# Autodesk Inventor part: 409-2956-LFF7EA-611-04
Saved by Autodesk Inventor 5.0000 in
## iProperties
Created: 2010-06
Part Number: 409-2956-LFF7EA-611-04
Cost Center: 0 lbmass
Material: A36 STEEL PLATE
Document SubType Name: Sheet Metal
Designer: S. Boerckel
Authority: 0 in^3
Mass: 31443.9 g
Surface Area: 6667.73 cm^2
Volume: 4000.49 cm^3
Density: 7.86 g/cm^3
Flat Pattern Width: 26.67 cm
Flat Pattern Length: 118.11 cm
Flat Pattern Area: 3149.99 cm^2
Sheet Metal Rule: 1/2"Thk
Sheet Metal Width: 16.0000 in
Sheet Metal Length: 80.0000 in^2
Description: PUMP FOOT PLATE
User Status: BURN
SaveDate: 2008-01-15
SaveTime: 10:24
FileName: Sheet Metal
Wide: =<Flat Pattern Width>cm
Length: =<Flat Pattern Length>cm
Thickness: 0.5000 in
SMR: =<Sheet Metal Rule> - <Material>
Author: S. Boerckel
Revision Number: 0
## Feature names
1. Plate1
